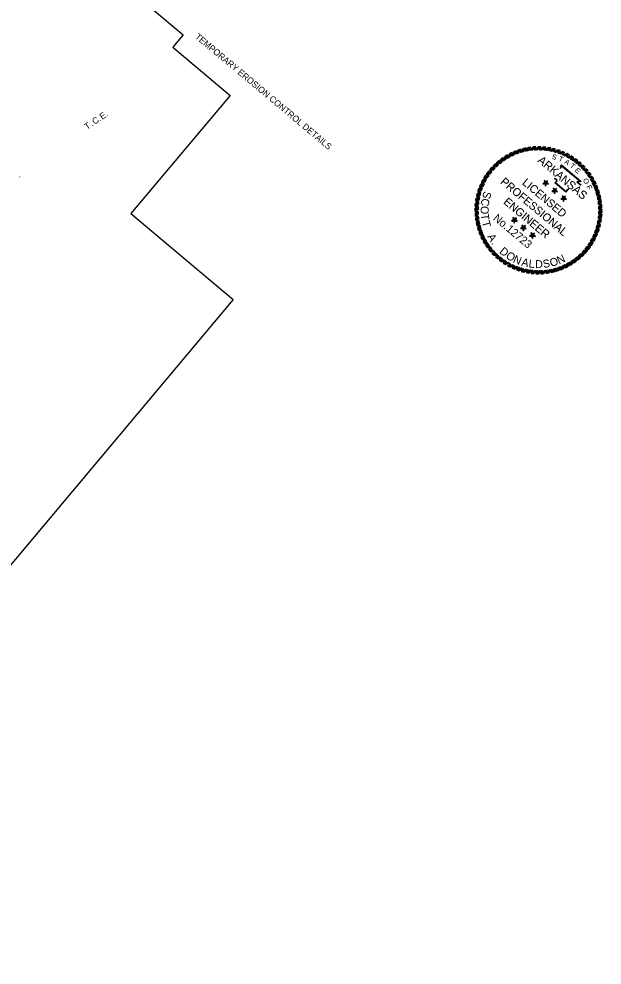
# Model space of a CAD drawing. Extents: x 1292584 to 1294692, y 222754 to 224578.
# Drawn here: x 1294135 to 1294692, y 222754 to 223658 of the extents above; entities that cross this region are included whole.
import ezdxf

# ---------------------------------------------------------------- set-up
doc = ezdxf.new("R2010")
doc.units = 0
for name, color, linetype in [('Default', 7, 'Continuous'), ('S_SHOULDER', 7, 'Continuous'), ('S_STORM_SEWER_ANNOT', 7, 'Continuous')]:
    doc.layers.add(name, color=color, linetype=linetype)

# ---------------------------------------------------------------- blocks, each defined once
blk = doc.blocks.new('STAR')
at = {"layer": 'Default'}
for p, q in [((0.059, 0.019), (-0.059, 0.019)), ((-0.059, 0.019), (0.036, -0.05)), ((0, 0.062), (-0.037, -0.05)), ((-0.036, -0.05), (0.059, 0.019)), ((-0.008, 0), (0.009, 0)), ((0.036, -0.05), (0, 0.062)), ((0, 0.006), (0, -0.008))]:
    blk.add_line(p, q, dxfattribs=at)
blk = doc.blocks.new('RP')
at = {"layer": 'Default'}
for p, q in [((-0.078, 1.266), (0.003, 1.33)), ((-0.058, 1.267), (0.022, 1.33)), ((-0.038, 1.267), (0.04, 1.329)), ((-0.018, 1.268), (0.059, 1.329))]:
    blk.add_line(p, q, dxfattribs=at)
for radius, start, end in [(1.268, 90.7933, 93.5307), (1.33, 87.4562, 89.8699)]:
    blk.add_arc((0, 0), radius, start, end, dxfattribs=at)

msp = doc.modelspace()

# ---------------------------------------------------------------- linework, layer by layer
at = {"layer": 'Default'}
for points in [[(1294652.27, 223515.21), (1294653.16, 223518.47), (1294671.95, 223502.72), (1294668.73, 223502.06), (1294670.02, 223501.01), (1294671.1, 223500.13), (1294672.07, 223499.12)], [(1294652.32, 223515.19), (1294653.22, 223518.45), (1294671.96, 223502.63), (1294668.73, 223501.99), (1294670.02, 223500.93), (1294671.09, 223500.05), (1294672.06, 223499.03)], [(1294652.65, 223515.1), (1294653.38, 223517.78), (1294671.09, 223502.94), (1294667.85, 223502.28), (1294669.77, 223500.71), (1294670.83, 223499.84), (1294671.79, 223498.85)], [(1294652.7, 223515.09), (1294653.43, 223517.76), (1294671.09, 223502.86), (1294667.85, 223502.21), (1294669.77, 223500.63), (1294670.83, 223499.76), (1294671.78, 223498.77)], [(1294660.41, 223494.97), (1294659.87, 223494.98), (1294659.44, 223494.68), (1294658.51, 223493.79), (1294657.42, 223492.49), (1294646.94, 223501.29), (1294648.41, 223503.04), (1294648.73, 223503.43), (1294648.42, 223503.92), (1294646.93, 223505.17), (1294647, 223505.8)], [(1294660.39, 223494.92), (1294659.85, 223494.93), (1294659.41, 223494.63), (1294658.49, 223493.75), (1294657.39, 223492.46), (1294646.94, 223501.29), (1294648.41, 223503.04), (1294648.74, 223503.43), (1294648.43, 223503.92), (1294646.94, 223505.17), (1294647.02, 223505.8)], [(1294660.41, 223495.36), (1294659.75, 223495.37), (1294659.19, 223494.98), (1294658.23, 223494.06), (1294657.37, 223493.04), (1294647.48, 223501.34), (1294648.71, 223502.79), (1294649.22, 223503.4), (1294648.71, 223504.18), (1294647.34, 223505.33), (1294647.39, 223505.75)], [(1294660.39, 223495.31), (1294659.73, 223495.32), (1294659.17, 223494.94), (1294658.2, 223494.02), (1294657.35, 223493), (1294647.48, 223501.34), (1294648.71, 223502.79), (1294649.22, 223503.4), (1294648.72, 223504.17), (1294647.35, 223505.33), (1294647.4, 223505.75)]]:
    msp.add_lwpolyline(points, dxfattribs=at)
at = {"layer": 'S_SHOULDER'}
msp.add_lwpolyline([(1292584.05, 223779.83), (1293254.04, 224578.3), (1294171.77, 223808.23), (1294139.92, 223770.28), (1294291.79, 223642.84), (1294281.83, 223630.97), (1294336.68, 223584.95), (1294241.87, 223471.95), (1294339.54, 223390), (1293806.17, 222754.35)], close=True, dxfattribs=at)
msp.add_lwpolyline([(1292584.05, 223779.83), (1293254.04, 224578.3), (1294171.77, 223808.23), (1294139.92, 223770.28), (1294291.79, 223642.84), (1294281.83, 223630.97), (1294336.68, 223584.95), (1294241.87, 223471.95), (1294339.54, 223390), (1293806.17, 222754.35)], close=True, dxfattribs=at)
msp.add_lwpolyline([(1292584.05, 223779.83), (1293254.04, 224578.3), (1294171.77, 223808.23), (1294139.92, 223770.28), (1294291.79, 223642.84), (1294281.83, 223630.97), (1294336.68, 223584.95), (1294241.87, 223471.95), (1294339.54, 223390), (1293806.17, 222754.35)], close=True, dxfattribs=at)
msp.add_lwpolyline([(1292584.05, 223779.83), (1293254.04, 224578.3), (1294171.77, 223808.23), (1294139.92, 223770.28), (1294291.79, 223642.84), (1294281.83, 223630.97), (1294336.68, 223584.95), (1294241.87, 223471.95), (1294339.54, 223390), (1293806.17, 222754.35)], close=True, dxfattribs=at)
msp.add_lwpolyline([(1292584.05, 223779.83), (1293254.04, 224578.3), (1294171.77, 223808.23), (1294139.92, 223770.28), (1294291.79, 223642.84), (1294281.83, 223630.97), (1294336.68, 223584.95), (1294241.87, 223471.95), (1294339.54, 223390), (1293806.17, 222754.35)], close=True, dxfattribs=at)
msp.add_lwpolyline([(1292584.05, 223779.83), (1293254.04, 224578.3), (1294171.77, 223808.23), (1294139.92, 223770.28), (1294291.79, 223642.84), (1294281.83, 223630.97), (1294336.68, 223584.95), (1294241.87, 223471.95), (1294339.54, 223390), (1293806.17, 222754.35)], close=True, dxfattribs=at)

# ---------------------------------------------------------------- block references
at = {"layer": 'Default'}
for name, p, xscale, yscale, rotation in [('RP', (1294631.37, 223475.15), 45.588276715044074, 45.58827671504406, 14.000000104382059), ('RP', (1294631.28, 223475.2), 45.58827671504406, 45.588276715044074, 13.804199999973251), ('RP', (1294631.37, 223475.15), 45.588276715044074, 45.58827671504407, 9.500000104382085), ('RP', (1294631.28, 223475.2), 45.58827671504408, 45.588276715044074, 9.304199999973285), ('RP', (1294631.37, 223475.15), 45.58827671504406, 45.58827671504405, 5.000000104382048), ('RP', (1294631.28, 223475.2), 45.58827671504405, 45.58827671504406, 4.804199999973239), ('RP', (1294631.37, 223475.15), 45.58827671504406, 45.58827671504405, 0.500000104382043), ('RP', (1294631.28, 223475.2), 45.58827671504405, 45.58827671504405, 0.3041999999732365), ('RP', (1294631.37, 223475.15), 45.58827671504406, 45.58827671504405, -3.9999998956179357), ('RP', (1294631.28, 223475.2), 45.58827671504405, 45.58827671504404, -4.195800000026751), ('RP', (1294631.37, 223475.15), 45.58827671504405, 45.58827671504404, -8.499999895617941), ('RP', (1294631.28, 223475.2), 45.58827671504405, 45.58827671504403, -8.695800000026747), ('RP', (1294631.37, 223475.15), 45.588276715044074, 45.58827671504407, -12.99999989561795), ('RP', (1294631.28, 223475.2), 45.58827671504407, 45.58827671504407, -13.195800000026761), ('RP', (1294631.37, 223475.15), 45.58827671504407, 45.588276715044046, -17.499999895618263), ('RP', (1294631.28, 223475.2), 45.58827671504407, 45.58827671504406, -17.695800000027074), ('RP', (1294631.37, 223475.15), 45.58827671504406, 45.58827671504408, 36.500000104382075), ('RP', (1294631.28, 223475.2), 45.58827671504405, 45.588276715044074, 36.30419999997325), ('RP', (1294631.37, 223475.15), 45.58827671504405, 45.58827671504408, 32.00000010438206), ('RP', (1294631.28, 223475.2), 45.58827671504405, 45.58827671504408, 31.804199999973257), ('RP', (1294631.37, 223475.15), 45.58827671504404, 45.588276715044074, 27.500000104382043), ('RP', (1294631.28, 223475.2), 45.58827671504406, 45.58827671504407, 27.30419999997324), ('RP', (1294631.37, 223475.15), 45.58827671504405, 45.58827671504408, 23.000000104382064), ('RP', (1294631.28, 223475.2), 45.58827671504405, 45.588276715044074, 22.804199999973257), ('RP', (1294631.37, 223475.15), 45.588276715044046, 45.58827671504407, 18.500000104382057), ('RP', (1294631.28, 223475.2), 45.58827671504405, 45.58827671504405, 18.30419999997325), ('RP', (1294631.37, 223475.15), 45.588276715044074, 45.58827671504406, -21.99999989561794), ('RP', (1294631.28, 223475.2), 45.588276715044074, 45.58827671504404, -22.19580000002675), ('RP', (1294631.37, 223475.15), 45.588276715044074, 45.58827671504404, -26.499999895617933), ('RP', (1294631.28, 223475.2), 45.58827671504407, 45.58827671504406, -26.69580000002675), ('RP', (1294631.37, 223475.15), 45.58827671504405, 45.58827671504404, -30.999999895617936), ('RP', (1294631.28, 223475.2), 45.58827671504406, 45.58827671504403, -31.195800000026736), ('RP', (1294631.37, 223475.15), 45.58827671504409, 45.588276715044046, -35.49999989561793), ('RP', (1294631.28, 223475.2), 45.58827671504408, 45.58827671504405, -35.69580000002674), ('RP', (1294631.37, 223475.15), 45.58827671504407, 45.58827671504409, 50.000000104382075), ('RP', (1294631.28, 223475.2), 45.58827671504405, 45.58827671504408, 49.80419999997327), ('RP', (1294631.37, 223475.15), 45.58827671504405, 45.58827671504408, 45.500000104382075), ('RP', (1294631.28, 223475.2), 45.58827671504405, 45.58827671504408, 45.30419999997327), ('RP', (1294631.37, 223475.15), 45.58827671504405, 45.588276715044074, 41.000000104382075), ('RP', (1294631.28, 223475.2), 45.58827671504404, 45.588276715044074, 40.80419999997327), ('RP', (1294631.37, 223475.15), 45.58827671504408, 45.58827671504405, -39.999999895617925), ('RP', (1294631.28, 223475.2), 45.58827671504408, 45.588276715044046, -40.19580000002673), ('RP', (1294631.37, 223475.15), 45.58827671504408, 45.58827671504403, -44.49999989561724), ('RP', (1294631.28, 223475.2), 45.588276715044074, 45.58827671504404, -44.69580000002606), ('RP', (1294631.37, 223475.15), 45.58827671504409, 45.58827671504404, -48.99999989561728), ('RP', (1294631.28, 223475.2), 45.588276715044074, 45.58827671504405, -49.19580000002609), ('RP', (1294631.28, 223475.2), 45.58827671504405, 45.58827671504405, 58.80419999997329), ('RP', (1294631.37, 223475.15), 45.588276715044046, 45.588276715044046, 59.000000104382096), ('RP', (1294631.37, 223475.15), 45.58827671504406, 45.588276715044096, 54.50000010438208), ('RP', (1294631.28, 223475.2), 45.58827671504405, 45.5882767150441, 54.30419999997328), ('RP', (1294631.37, 223475.15), 45.58827671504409, 45.58827671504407, -53.49999989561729), ('RP', (1294631.28, 223475.2), 45.58827671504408, 45.588276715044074, -53.695800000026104), ('RP', (1294631.37, 223475.15), 45.588276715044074, 45.58827671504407, -57.99999989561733), ('RP', (1294631.28, 223475.2), 45.588276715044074, 45.58827671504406, -58.19580000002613), ('RP', (1294631.28, 223475.2), 45.588276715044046, 45.58827671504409, 67.80419999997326), ('RP', (1294631.37, 223475.15), 45.58827671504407, 45.58827671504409, 68.00000010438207), ('RP', (1294631.28, 223475.2), 45.588276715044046, 45.58827671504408, 63.30419999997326), ('RP', (1294631.37, 223475.15), 45.588276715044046, 45.58827671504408, 63.50000010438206), ('STAR', (1294638.16, 223501.08), 45.58827671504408, 45.588276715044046, -40.19580000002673), ('STAR', (1294638.17, 223501.05), 45.58827671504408, 45.58827671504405, -39.999999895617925), ('STAR', (1294646.78, 223493.8), 45.58827671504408, 45.588276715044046, -40.19580000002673), ('STAR', (1294646.8, 223493.8), 45.58827671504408, 45.58827671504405, -39.999999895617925), ('RP', (1294631.37, 223475.15), 45.588276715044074, 45.58827671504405, -62.49999989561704), ('RP', (1294631.28, 223475.2), 45.588276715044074, 45.58827671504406, -62.695800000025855), ('RP', (1294631.37, 223475.15), 45.58827671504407, 45.58827671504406, -66.99999989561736), ('RP', (1294631.28, 223475.2), 45.58827671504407, 45.588276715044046, -67.19580000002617), ('RP', (1294631.28, 223475.2), 45.58827671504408, 45.588276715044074, -71.69580000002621), ('RP', (1294631.37, 223475.15), 45.58827671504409, 45.588276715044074, -71.49999989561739), ('RP', (1294631.28, 223475.2), 45.58827671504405, 45.58827671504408, 76.80419999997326), ('RP', (1294631.37, 223475.15), 45.588276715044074, 45.58827671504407, 77.00000010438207), ('RP', (1294631.28, 223475.2), 45.588276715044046, 45.58827671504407, 72.30419999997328), ('RP', (1294631.37, 223475.15), 45.588276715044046, 45.58827671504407, 72.5000001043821), ('STAR', (1294655.39, 223486.52), 45.58827671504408, 45.588276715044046, -40.19580000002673), ('STAR', (1294655.44, 223486.55), 45.58827671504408, 45.58827671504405, -39.999999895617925), ('RP', (1294631.28, 223475.2), 45.58827671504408, 45.58827671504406, -76.19580000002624), ('RP', (1294631.37, 223475.15), 45.58827671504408, 45.588276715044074, -75.99999989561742), ('RP', (1294631.37, 223475.15), 45.58827671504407, 45.588276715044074, -80.49999989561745), ('RP', (1294631.28, 223475.2), 45.588276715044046, 45.58827671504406, 85.80419999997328), ('RP', (1294631.37, 223475.15), 45.588276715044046, 45.58827671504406, 86.0000001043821), ('RP', (1294631.28, 223475.2), 45.58827671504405, 45.58827671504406, 81.30419999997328), ('RP', (1294631.37, 223475.15), 45.58827671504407, 45.58827671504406, 81.50000010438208), ('RP', (1294631.28, 223475.2), 45.58827671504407, 45.58827671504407, -80.69580000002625), ('RP', (1294631.28, 223475.2), 45.58827671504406, 45.58827671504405, -85.19580000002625), ('RP', (1294631.37, 223475.15), 45.58827671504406, 45.58827671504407, -84.99999989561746), ('RP', (1294631.28, 223475.2), 45.588276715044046, 45.58827671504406, 90.30419999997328), ('RP', (1294631.28, 223475.2), 45.58827671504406, 45.58827671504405, 94.80419999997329), ('RP', (1294631.37, 223475.15), 45.58827671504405, 45.58827671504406, 90.50000010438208), ('RP', (1294631.37, 223475.15), 45.58827671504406, 45.58827671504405, 95.0000001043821), ('RP', (1294631.28, 223475.2), 45.58827671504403, 45.588276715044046, -94.19580000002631), ('RP', (1294631.37, 223475.15), 45.588276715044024, 45.58827671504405, -93.99999989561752), ('RP', (1294631.28, 223475.2), 45.588276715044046, 45.588276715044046, -89.6958000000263), ('RP', (1294631.37, 223475.15), 45.58827671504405, 45.58827671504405, -89.49999989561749), ('RP', (1294631.28, 223475.2), 45.58827671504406, 45.58827671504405, 99.30419999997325), ('RP', (1294631.37, 223475.15), 45.58827671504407, 45.58827671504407, 99.50000010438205), ('RP', (1294631.28, 223475.2), 45.58827671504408, 45.58827671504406, 103.80419999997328), ('RP', (1294631.37, 223475.15), 45.58827671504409, 45.58827671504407, 104.00000010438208), ('STAR', (1294608.32, 223465.76), 45.58827671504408, 45.588276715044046, -40.19580000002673), ('STAR', (1294608.44, 223465.63), 45.58827671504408, 45.58827671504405, -39.999999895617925), ('STAR', (1294616.94, 223458.48), 45.58827671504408, 45.588276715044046, -40.19580000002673), ('STAR', (1294617.08, 223458.38), 45.58827671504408, 45.58827671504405, -39.999999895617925), ('RP', (1294631.28, 223475.2), 45.588276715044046, 45.58827671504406, -103.19580000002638), ('RP', (1294631.37, 223475.15), 45.58827671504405, 45.588276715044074, -102.99999989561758), ('RP', (1294631.28, 223475.2), 45.58827671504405, 45.58827671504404, -98.69580000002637), ('RP', (1294631.37, 223475.15), 45.588276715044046, 45.58827671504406, -98.49999989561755), ('RP', (1294631.28, 223475.2), 45.58827671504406, 45.588276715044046, 108.30419999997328), ('RP', (1294631.37, 223475.15), 45.58827671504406, 45.58827671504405, 108.50000010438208), ('RP', (1294631.28, 223475.2), 45.58827671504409, 45.58827671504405, 112.80419999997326), ('RP', (1294631.37, 223475.15), 45.588276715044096, 45.58827671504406, 113.00000010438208), ('STAR', (1294625.55, 223451.2), 45.58827671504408, 45.588276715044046, -40.19580000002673), ('STAR', (1294625.72, 223451.13), 45.58827671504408, 45.58827671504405, -39.999999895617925), ('RP', (1294631.28, 223475.2), 45.588276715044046, 45.588276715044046, -116.69580000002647), ('RP', (1294631.37, 223475.15), 45.58827671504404, 45.588276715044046, -116.49999989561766), ('RP', (1294631.28, 223475.2), 45.58827671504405, 45.588276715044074, -112.19580000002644), ('RP', (1294631.37, 223475.15), 45.58827671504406, 45.58827671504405, -111.99999989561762), ('RP', (1294631.28, 223475.2), 45.58827671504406, 45.58827671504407, -107.69580000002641), ('RP', (1294631.37, 223475.15), 45.58827671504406, 45.58827671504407, -107.49999989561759), ('RP', (1294631.28, 223475.2), 45.58827671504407, 45.58827671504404, 117.3041999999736), ('RP', (1294631.37, 223475.15), 45.58827671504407, 45.588276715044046, 117.50000010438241), ('RP', (1294631.28, 223475.2), 45.588276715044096, 45.588276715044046, 121.80419999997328), ('RP', (1294631.37, 223475.15), 45.588276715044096, 45.588276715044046, 122.00000010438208), ('RP', (1294631.28, 223475.2), 45.58827671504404, 45.58827671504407, -125.69580000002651), ('RP', (1294631.37, 223475.15), 45.58827671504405, 45.58827671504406, -125.4999998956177), ('RP', (1294631.28, 223475.2), 45.588276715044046, 45.58827671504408, -121.1958000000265), ('RP', (1294631.37, 223475.15), 45.58827671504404, 45.588276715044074, -120.99999989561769), ('RP', (1294631.28, 223475.2), 45.588276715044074, 45.58827671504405, 126.30419999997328), ('RP', (1294631.37, 223475.15), 45.58827671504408, 45.588276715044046, 126.50000010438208), ('RP', (1294631.28, 223475.2), 45.58827671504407, 45.588276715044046, 130.8041999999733), ('RP', (1294631.37, 223475.15), 45.58827671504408, 45.58827671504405, 131.00000010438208), ('RP', (1294631.28, 223475.2), 45.58827671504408, 45.588276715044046, 135.30419999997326), ('RP', (1294631.37, 223475.15), 45.58827671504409, 45.58827671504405, 135.50000010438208), ('RP', (1294631.28, 223475.2), 45.58827671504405, 45.58827671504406, -134.69580000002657), ('RP', (1294631.37, 223475.15), 45.58827671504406, 45.588276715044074, -134.49999989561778), ('RP', (1294631.28, 223475.2), 45.588276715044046, 45.58827671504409, -130.19580000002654), ('RP', (1294631.37, 223475.15), 45.58827671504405, 45.58827671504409, -129.99999989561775), ('RP', (1294631.28, 223475.2), 45.58827671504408, 45.588276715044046, 139.80419999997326), ('RP', (1294631.37, 223475.15), 45.588276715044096, 45.58827671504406, 140.00000010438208), ('RP', (1294631.28, 223475.2), 45.588276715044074, 45.58827671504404, 144.30419999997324), ('RP', (1294631.37, 223475.15), 45.58827671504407, 45.588276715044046, 144.50000010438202), ('RP', (1294631.28, 223475.2), 45.58827671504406, 45.58827671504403, 148.80419999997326), ('RP', (1294631.37, 223475.15), 45.58827671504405, 45.58827671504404, 149.00000010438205), ('RP', (1294631.28, 223475.2), 45.58827671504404, 45.588276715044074, -152.69580000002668), ('RP', (1294631.37, 223475.15), 45.588276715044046, 45.58827671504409, -152.4999998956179), ('RP', (1294631.28, 223475.2), 45.588276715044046, 45.58827671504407, -148.19580000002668), ('RP', (1294631.37, 223475.15), 45.588276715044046, 45.58827671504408, -147.99999989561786), ('RP', (1294631.28, 223475.2), 45.58827671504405, 45.58827671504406, -143.69580000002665), ('RP', (1294631.37, 223475.15), 45.58827671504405, 45.588276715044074, -143.49999989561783), ('RP', (1294631.28, 223475.2), 45.58827671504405, 45.588276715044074, -139.1958000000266), ('RP', (1294631.37, 223475.15), 45.58827671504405, 45.58827671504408, -138.99999989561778), ('RP', (1294631.28, 223475.2), 45.588276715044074, 45.58827671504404, 153.30419999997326), ('RP', (1294631.37, 223475.15), 45.58827671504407, 45.58827671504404, 153.50000010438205), ('RP', (1294631.28, 223475.2), 45.588276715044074, 45.58827671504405, 157.8041999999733), ('RP', (1294631.37, 223475.15), 45.58827671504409, 45.58827671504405, 158.00000010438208), ('RP', (1294631.28, 223475.2), 45.58827671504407, 45.58827671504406, 162.3041999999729), ('RP', (1294631.37, 223475.15), 45.58827671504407, 45.58827671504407, 162.50000010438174), ('RP', (1294631.28, 223475.2), 45.58827671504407, 45.58827671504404, 166.8041999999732), ('RP', (1294631.37, 223475.15), 45.58827671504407, 45.58827671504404, 167.00000010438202), ('RP', (1294631.28, 223475.2), 45.58827671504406, 45.588276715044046, 171.30419999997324), ('RP', (1294631.37, 223475.15), 45.58827671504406, 45.58827671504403, 171.50000010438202), ('RP', (1294631.28, 223475.2), 45.58827671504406, 45.58827671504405, 175.80419999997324), ('RP', (1294631.37, 223475.15), 45.588276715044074, 45.58827671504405, 176.00000010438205), ('RP', (1294631.28, 223475.2), 45.58827671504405, 45.58827671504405, -179.69580000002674), ('RP', (1294631.37, 223475.15), 45.58827671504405, 45.58827671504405, -179.49999989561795), ('RP', (1294631.28, 223475.2), 45.58827671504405, 45.58827671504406, -175.19580000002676), ('RP', (1294631.37, 223475.15), 45.58827671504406, 45.58827671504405, -174.99999989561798), ('RP', (1294631.28, 223475.2), 45.58827671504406, 45.58827671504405, -170.6958000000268), ('RP', (1294631.37, 223475.15), 45.58827671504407, 45.58827671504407, -170.499999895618), ('RP', (1294631.28, 223475.2), 45.58827671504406, 45.58827671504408, -166.19580000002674), ('RP', (1294631.37, 223475.15), 45.588276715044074, 45.58827671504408, -165.99999989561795), ('RP', (1294631.28, 223475.2), 45.58827671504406, 45.588276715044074, -161.6958000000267), ('RP', (1294631.37, 223475.15), 45.58827671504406, 45.58827671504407, -161.49999989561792), ('RP', (1294631.28, 223475.2), 45.58827671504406, 45.58827671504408, -157.1958000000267), ('RP', (1294631.37, 223475.15), 45.58827671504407, 45.58827671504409, -156.99999989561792)]:
    msp.add_blockref(name, p, dxfattribs=dict(at, xscale=xscale, yscale=yscale, rotation=rotation))

# ---------------------------------------------------------------- texts
for s, height, rotation, p in [('ARKANSAS', 7.894, 320, (1294629.8, 223521.81)), ('ARKANSAS', 7.894, 319.8042, (1294629.87, 223521.86)), ('S', 4.84, 339.77256, (1294643.53, 223524.65)), ('S', 4.84, 339.57676, (1294643.61, 223524.66)), ('T', 4.84, 336.90148, (1294650.01, 223522.81)), ('T', 4.84, 336.70568, (1294650.09, 223522.8)), ('A', 4.84, 328.67877, (1294655.5, 223520.21)), ('A', 4.84, 328.48297, (1294655.56, 223520.18)), ('T', 4.84, 321.47887, (1294660.9, 223516.93)), ('T', 4.84, 321.28307, (1294660.95, 223516.88)), ('E', 4.84, 316.67203, (1294665.55, 223512.84)), ('E', 4.84, 316.47623, (1294665.59, 223512.78)), ('PROFESSIONAL', 7.6424, 319.8042, (1294594.35, 223501.41)), ('PROFESSIONAL', 7.6424, 320, (1294594.35, 223501.23)), ('LICENSED', 7.642, 319.8042, (1294615.11, 223500.6)), ('LICENSED', 7.642, 320, (1294615.11, 223500.49)), ('O', 4.84, 301.2218, (1294673.48, 223504.02)), ('O', 4.84, 301.026, (1294673.49, 223503.93)), ('F', 4.84, 295.16702, (1294676.82, 223497.78)), ('F', 4.84, 295.36282, (1294676.83, 223497.88)), ('S', 7.64, 253.94855, (1294579.28, 223493.93)), ('C', 7.64, 261.49729, (1294577.26, 223486.93)), ('ENGINEER', 7.642, 319.8042, (1294597.22, 223482.25)), ('ENGINEER', 7.642, 320, (1294597.28, 223482.08)), ('O', 7.64, 269.42346, (1294576.16, 223479.35)), ('T', 7.64, 277.72707, (1294576.13, 223471.34)), ('No.12723', 7.612, 320, (1294587.42, 223466.57)), ('T', 7.64, 285.27581, (1294577.11, 223464.11)), ('A', 7.64, 300.75072, (1294582.02, 223450.04)), ('.', 7.64, 308.29946, (1294585.75, 223443.77)), ('D', 7.64, 320.37744, (1294593.33, 223434.93)), ('O', 7.64, 328.68105, (1294599.54, 223429.85)), ('N', 7.64, 336.98466, (1294606.41, 223425.73)), ('A', 7.64, 346.04314, (1294614.51, 223422.42)), ('L', 7.64, 353.59188, (1294621.58, 223420.66)), ('D', 7.64, 0.38575, (1294628.09, 223419.89)), ('S', 7.64, 8.68936, (1294636.11, 223420)), ('O', 7.64, 16.23809, (1294643.32, 223421.1)), ('N', 7.64, 24.5417, (1294651, 223423.39))]:
    msp.add_text(s, height=height, rotation=rotation, dxfattribs=at).set_placement(p)
at = {"layer": 'S_STORM_SEWER_ANNOT'}
for s, rotation, p in [('TEMPORARY EROSION CONTROL DETAILS', 320, (1294302.63, 223640.02)), ('C', 33.48443, (1294207.21, 223556.71)), ('E', 33.48443, (1294214.39, 223561.45)), ('.', 33.48443, (1294211.94, 223559.84)), ('.', 33.48443, (1294218.88, 223564.42)), ('T', 33.48443, (1294199.88, 223551.86)), ('.', 33.48443, (1294204.77, 223555.09)), ('.', 21.6622, (1294134.89, 223506.16))]:
    msp.add_text(s, height=6, rotation=rotation, dxfattribs=at).set_placement(p)

doc.saveas('drawing.dxf')
